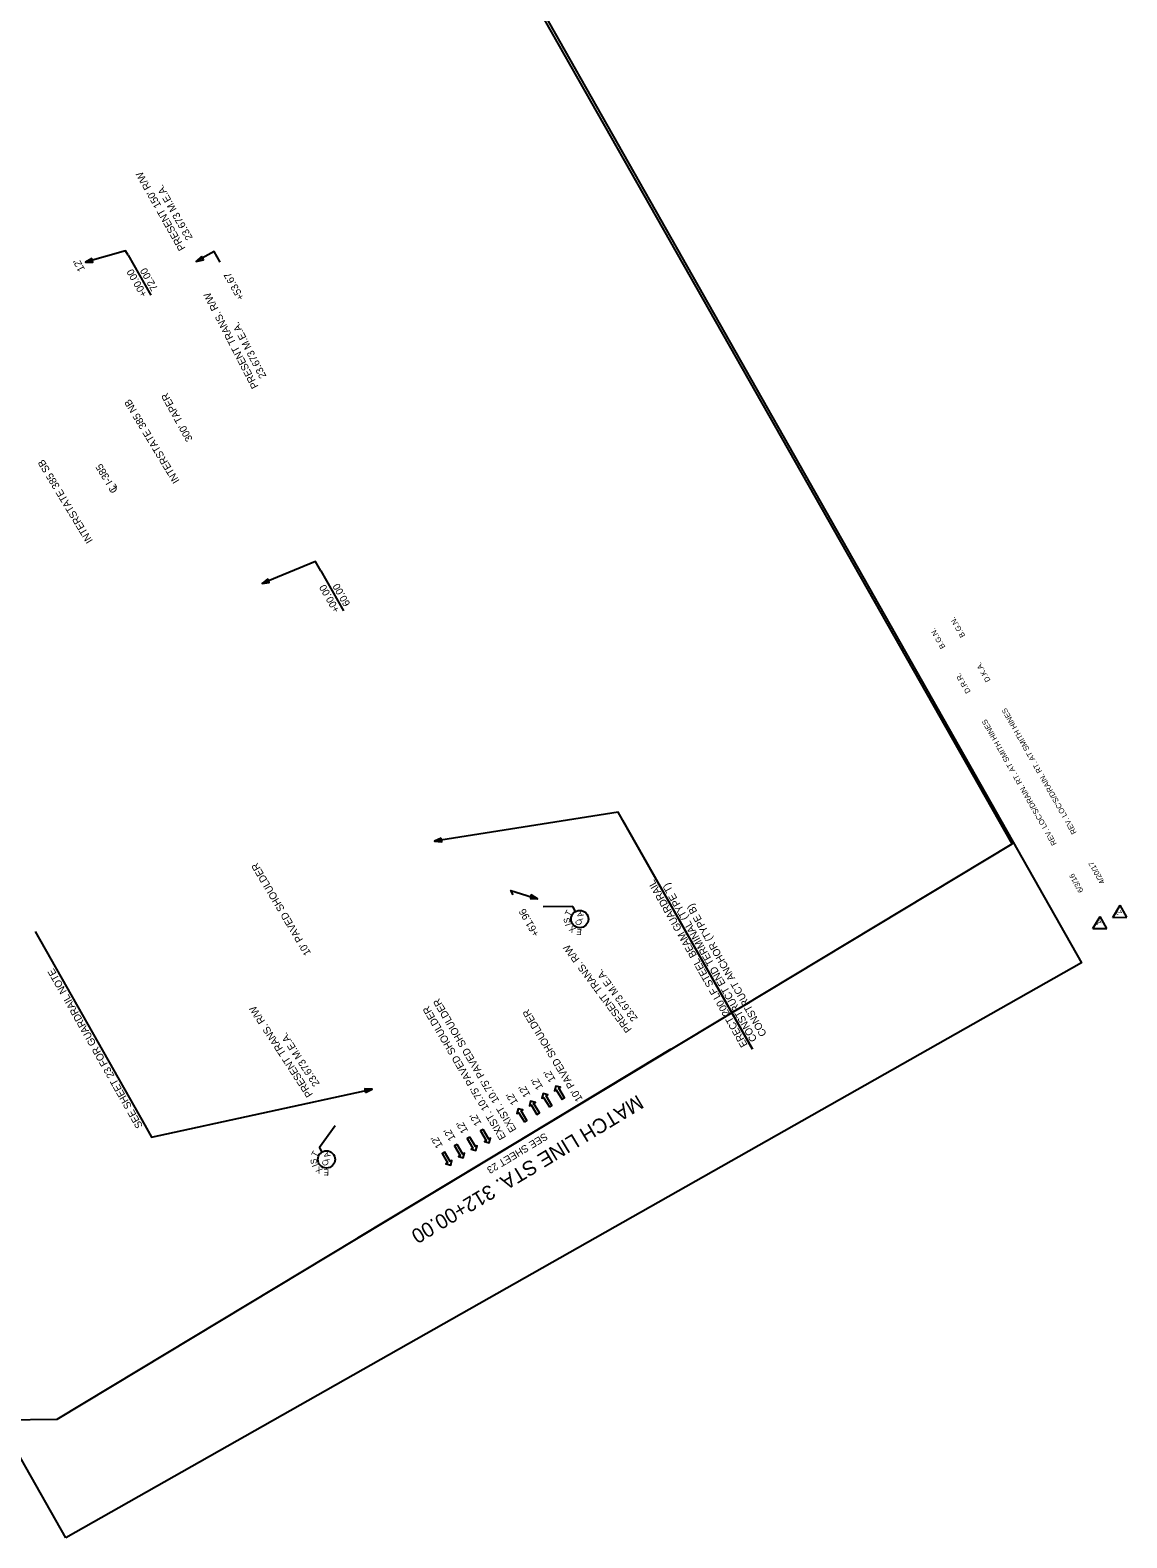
# Model space of a CAD drawing. Extents: x 1612404 to 1614220, y 1085556 to 1087485.
# Drawn here: x 1613322 to 1614220, y 1085556 to 1086792 of the extents above; entities that cross this region are included whole.
import ezdxf

# ---------------------------------------------------------------- set-up
doc = ezdxf.new("R2010")
doc.units = 0
for name, color, linetype in [('RD_EX_BldgApp', 7, 'Continuous'), ('RD_EX_Driveway', 7, 'Continuous'), ('RD_EX_DV_TX_Gov', 7, 'Continuous'), ('RD_EX_Fence_Other', 7, 'Continuous'), ('RD_EX_H2O_WetLd', 7, 'Continuous'), ('RD_EX_Misc', 7, 'Continuous'), ('RD_EX_Misc_Golf_Teebox', 7, 'Continuous'), ('RD_EX_UT', 7, 'Continuous'), ('RD_EX_VEG', 7, 'Continuous')]:
    doc.layers.add(name, color=color, linetype=linetype)

msp = doc.modelspace()

# ---------------------------------------------------------------- linework, layer by layer
at = {"layer": 'RD_EX_BldgApp'}
for points in [[(1613477.4, 1086601.6), (1613472.4, 1086610.3), (1613457.8, 1086602)], [(1613717.6, 1086083), (1613715.6, 1086086.5), (1613737.5, 1086079.8)]]:
    msp.add_lwpolyline(points, dxfattribs=at)
for points in [[(1613462.1, 1086606.2), (1613457.8, 1086602), (1613463.6, 1086603.5)], [(1613731.5, 1086080), (1613737.5, 1086079.8), (1613732.4, 1086083)]]:
    msp.add_lwpolyline(points, close=True, dxfattribs=at)
at = {"layer": 'RD_EX_Driveway'}
for p, q in [((1613807.2, 1086144.4), (1613913.6, 1085956.6)), ((1613325.7, 1086053.1), (1613415.5, 1085894.4))]:
    msp.add_line(p, q, dxfattribs=at)
for points in [[(1613913.6, 1085956.6), (1613803.6, 1086150.9), (1613653, 1086127)], [(1613415.5, 1085894.4), (1613421.1, 1085884.5), (1613602, 1085923.9)]]:
    msp.add_lwpolyline(points, dxfattribs=at)
for points in [[(1613658.5, 1086129.4), (1613653, 1086127), (1613659, 1086126.4)], [(1613596.6, 1085921.2), (1613602, 1085923.9), (1613596, 1085924.2)]]:
    msp.add_lwpolyline(points, close=True, dxfattribs=at)
at = {"layer": 'RD_EX_DV_TX_Gov'}
for p, q in [((1613766.4, 1086073.4), (1613742.2, 1086073.2)), ((1613768.6, 1086069.4), (1613766.4, 1086073.4)), ((1613558.7, 1085876.3), (1613571.7, 1085893.9)), ((1613561, 1085872.3), (1613558.7, 1085876.3))]:
    msp.add_line(p, q, dxfattribs=at)
for centre in [(1613772.1, 1086063.2), (1613564.5, 1085866.2)]:
    msp.add_circle(centre, 7.08, dxfattribs=at)
at = {"layer": 'RD_EX_Fence_Other'}
msp.add_lwpolyline([(1613350.8, 1085556.1), (1612525.6, 1087013.7), (1613357.9, 1087484.9), (1614183.2, 1086027.3)], close=True, dxfattribs=at)
at = {"layer": 'RD_EX_Misc'}
for points in [[(1613747.3, 1085909.3), (1613749.3, 1085910.5), (1613744.6, 1085918.3), (1613746, 1085919.2), (1613742.1, 1085920.2), (1613741.1, 1085916.3), (1613742.5, 1085917.1)], [(1613757.6, 1085915.4), (1613759.6, 1085916.7), (1613754.9, 1085924.5), (1613756.3, 1085925.4), (1613752.4, 1085926.3), (1613751.4, 1085922.5), (1613752.8, 1085923.3)], [(1613726.7, 1085896.9), (1613728.8, 1085898.1), (1613724, 1085906), (1613725.4, 1085906.8), (1613721.6, 1085907.8), (1613720.6, 1085903.9), (1613722, 1085904.7)], [(1613737, 1085903.1), (1613739.1, 1085904.3), (1613734.3, 1085912.2), (1613735.7, 1085913), (1613731.8, 1085914), (1613730.9, 1085910.1), (1613732.3, 1085910.9)], [(1613681.9, 1085884.6), (1613679.9, 1085883.4), (1613684.5, 1085875.5), (1613683.1, 1085874.6), (1613687, 1085873.6), (1613688, 1085877.5), (1613686.6, 1085876.7)], [(1613692.9, 1085890.8), (1613690.8, 1085889.6), (1613695.4, 1085881.7), (1613694, 1085880.8), (1613697.9, 1085879.8), (1613698.9, 1085883.7), (1613697.5, 1085882.9)], [(1613661.2, 1085872.4), (1613659.2, 1085871.2), (1613663.8, 1085863.3), (1613662.4, 1085862.5), (1613666.3, 1085861.5), (1613667.3, 1085865.3), (1613665.9, 1085864.5)], [(1613671.6, 1085878.5), (1613669.5, 1085877.3), (1613674.2, 1085869.4), (1613672.8, 1085868.6), (1613676.6, 1085867.6), (1613677.6, 1085871.4), (1613676.2, 1085870.6)]]:
    msp.add_lwpolyline(points, close=True, dxfattribs=at)
at = {"layer": 'RD_EX_Misc_Golf_Teebox'}
for p, q in [((1613402, 1086607.2), (1613420.5, 1086574.4)), ((1613559.8, 1086348.6), (1613578.4, 1086315.8)), ((1614192.6, 1086055.4), (1614198.6, 1086065.4)), ((1614204.2, 1086055.5), (1614198.6, 1086065.4)), ((1614208.9, 1086064.6), (1614214.9, 1086074.6)), ((1614208.9, 1086064.6), (1614220.5, 1086064.7)), ((1614220.5, 1086064.7), (1614214.9, 1086074.6)), ((1614192.6, 1086055.4), (1614204.2, 1086055.5))]:
    msp.add_line(p, q, dxfattribs=at)
for points in [[(1613402, 1086607.2), (1613399.9, 1086610.8), (1613367.1, 1086601.5)], [(1613559.8, 1086348.6), (1613555.4, 1086356.3), (1613511.7, 1086338.3)]]:
    msp.add_lwpolyline(points, dxfattribs=at)
for points in [[(1613372.2, 1086604.5), (1613367.1, 1086601.5), (1613373.1, 1086601.5)], [(1613516.4, 1086342), (1613511.7, 1086338.3), (1613517.6, 1086339.1)]]:
    msp.add_lwpolyline(points, close=True, dxfattribs=at)
at = {"layer": 'RD_EX_UT'}
msp.add_lwpolyline([(1613343.7, 1085653.3), (1614126.4, 1086125), (1613415.2, 1087379), (1613116.7, 1087245.1), (1612843.1, 1087121.9), (1612576.5, 1087002), (1612672.7, 1086832.1), (1612642.4, 1086814.9), (1613299.9, 1085652.9)], close=True, dxfattribs=at)
msp.add_lwpolyline([(1613343.7, 1085653.3), (1614126.4, 1086125), (1613415.2, 1087379), (1613116.7, 1087245.1), (1612843.1, 1087121.9), (1612576.5, 1087002), (1612672.7, 1086832.1), (1612642.4, 1086814.9), (1613299.9, 1085652.9)], close=True, dxfattribs=at)
msp.add_lwpolyline([(1613343.7, 1085653.3), (1614126.4, 1086125), (1613415.2, 1087379), (1613116.7, 1087245.1), (1612843.1, 1087121.9), (1612576.5, 1087002), (1612672.7, 1086832.1), (1612642.4, 1086814.9), (1613299.9, 1085652.9)], close=True, dxfattribs=at)
at = {"layer": 'RD_EX_VEG'}
msp.add_lwpolyline([(1613846.8, 1085956.5), (1613718.4, 1085879.1), (1613589.9, 1085801.7)], dxfattribs=at)

# ---------------------------------------------------------------- texts
at = {"layer": 'RD_EX_BldgApp'}
for s, rotation, p in [("PRESENT 150' R/W ", 119.5163, (1613449.1, 1086613)), ('  23.673 M.E.A.', 119.5163, (1613457.3, 1086617.7)), ('+53.67', 119.5163, (1613497.4, 1086572.4)), ('PRESENT TRANS. R/W ', 117.3244, (1613509, 1086499.8)), ('  23.673 M.E.A.', 117.3244, (1613517.5, 1086504.1)), ('+61.96', 119.5163, (1613739.2, 1086050.9)), ('PRESENT TRANS. R/W ', 126.574, (1613815, 1085972.8)), ('  23.673 M.E.A.', 126.574, (1613822.6, 1085978.4)), ('PRESENT TRANS. R/W ', 123.0769, (1613553.6, 1085919.5)), ('  23.673 M.E.A.', 123.0769, (1613561.6, 1085924.6))]:
    msp.add_text(s, height=6, rotation=rotation, dxfattribs=at).set_placement(p)
at = {"layer": 'RD_EX_Driveway'}
for s, rotation, p in [('ERECT 200 LF STEEL BEAM GUARDRAIL', 119.518, (1613909.8, 1085960.2)), ('CONSTRUCT END TERMINAL (TYPE T)', 119.518, (1613917.7, 1085964.6)), ('CONSTRUCT ANCHOR (TYPE B)', 119.518, (1613925.5, 1085969)), ('SEE SHEET 23 FOR GUARDRAIL NOTE', 119.5163, (1613414.2, 1085893.7))]:
    msp.add_text(s, height=6, rotation=rotation, dxfattribs=at).set_placement(p)
at = {"layer": 'RD_EX_DV_TX_Gov'}
for s, rotation, p in [('T', 60.6143, (1613763.9, 1086065.1)), ('A', 119.5131, (1613775.7, 1086066.3)), ('S', 95.7757, (1613764.3, 1086060.1)), ('I', 107.4962, (1613765.1, 1086058.5)), ('X', 142.6577, (1613769.1, 1086055.4)), ('C', 119.5131, (1613774.6, 1086059.6)), ('/', 119.5131, (1613775, 1086063.2)), ('E', 176.1448, (1613773.9, 1086055)), ('S', 97.7279, (1613556.8, 1085862.7)), ('T', 62.5664, (1613556.2, 1085867.8)), ('/', 119.5131, (1613567.3, 1085866.2)), ('A', 119.5131, (1613568.1, 1085869.3)), ('I', 109.4484, (1613557.7, 1085861.2)), ('X', 144.6099, (1613561.7, 1085858.2)), ('C', 119.5131, (1613567, 1085862.6)), ('E', 178.097, (1613566.6, 1085858))]:
    msp.add_text(s, height=5, rotation=rotation, dxfattribs=at).set_placement(p)
at = {"layer": 'RD_EX_H2O_WetLd'}
for s, p in [('INTERSTATE 385 NB', (1613444.3, 1086422.4)), ('INTERSTATE 385 SB', (1613373.2, 1086373.3)), ('C I-385', (1613393.6, 1086414.5)), ('L', (1613393.4, 1086416.7))]:
    msp.add_text(s, height=6, rotation=121.1424, dxfattribs=at).set_placement(p)
at = {"layer": 'RD_EX_Misc_Golf_Teebox'}
for s, height, rotation, p in [("12'", 6, 118.7862, (1613366.7, 1086595.8)), ('+00.00', 6, 119.5163, (1613417.8, 1086575.1)), ('72.00', 6, 119.5163, (1613426.5, 1086580.1)), ("300' TAPER", 6, 118.7862, (1613455.1, 1086456.5)), ('+00.00', 6, 119.5163, (1613575.6, 1086316.5)), ('60.00', 6, 119.5163, (1613584.3, 1086321.5)), ('B.G.N.', 4.4, 119.5163, (1614071.9, 1086286.2)), ('B.G.N.', 4.4, 119.5163, (1614088.2, 1086295.4)), ('D.R.R.', 4.4, 119.5163, (1614092.6, 1086249.6)), ('D.K.A.', 4.4, 119.5163, (1614108.9, 1086258.9)), ("REV. LOC'S/DRAIN. RT. AT SMITH HINES", 4.4, 119.5163, (1614179.5, 1086134.2)), ("REV. LOC'S/DRAIN. RT. AT SMITH HINES", 4.4, 119.5163, (1614163.2, 1086125)), ("10' PAVED SHOULDER", 6, 120.7284, (1613552, 1086035.4)), ('4/20/17', 4.4, 119.5163, (1614202.6, 1086093.3)), ('6/3/16', 4.4, 119.5163, (1614185.1, 1086086.3)), ('2', 4.4, 119.5163, (1614216.7, 1086068)), ('1', 4.4, 119.5163, (1614200, 1086059.6)), ("EXIST. 10.75' PAVED SHOULDER", 6, 120.5175, (1613711.9, 1085884.4)), ("EXIST. 10.75' PAVED SHOULDER", 6, 120.5175, (1613720.4, 1085890.6)), ("10' PAVED SHOULDER", 6, 121.0752, (1613774.7, 1085915.7)), ("12'", 6, 121.0735, (1613742.2, 1085925.4)), ("12'", 6, 121.0735, (1613752.5, 1085931.6)), ("12'", 6, 121.0735, (1613721.7, 1085913)), ("12'", 6, 121.0735, (1613731.9, 1085919.2)), ("12'", 6, 120.4142, (1613680.8, 1085889.6)), ("12'", 6, 120.4142, (1613691.8, 1085895.8)), ("12'", 6, 120.4142, (1613660.1, 1085877.4)), ("12'", 6, 120.4142, (1613670.5, 1085883.5))]:
    msp.add_text(s, height=height, rotation=rotation, dxfattribs=at).set_placement(p)
at = {"layer": 'RD_EX_VEG'}
for s, height, p in [('MATCH LINE STA. 312+00.00', 12, (1613819.5, 1085919.6)), ('SEE SHEET 23', 6, (1613743.5, 1085888.3))]:
    msp.add_text(s, height=height, rotation=211.1281, dxfattribs=at).set_placement(p)

doc.saveas('drawing.dxf')
